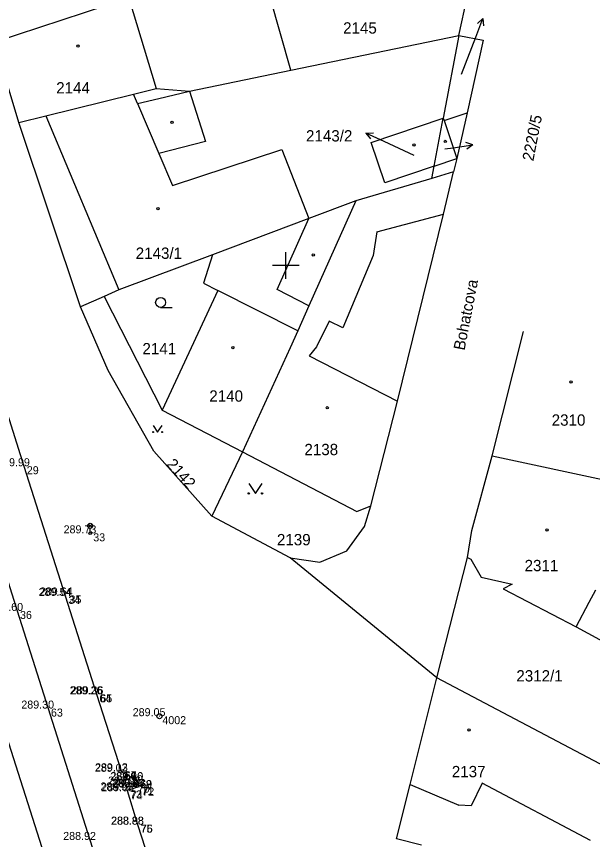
# Model space of a CAD drawing. Extents: x -599970 to -599524, y -1154772 to -1154457.
# Drawn here: x -599670.2 to -599627, y -1154593 to -1154531.3 of the extents above; entities that cross this region are included whole.
import ezdxf

# ---------------------------------------------------------------- set-up
doc = ezdxf.new("R2010")
doc.units = 0
for name, color, linetype in [('Z-ELEKTRICKE SKRINE LAMPY', 7, 'Continuous'), ('Z-KANALIZACNI SACHTY VPUSTI', 7, 'Continuous'), ('Z-KATASTRALNI MAPA', 7, 'Continuous'), ('Z-KRIZKY CTVERCOVE SITE', 7, 'Continuous'), ('Z-PEVNE BODY-CISLO', 7, 'Continuous'), ('Z-PEVNE BODY-VYSKA', 7, 'Continuous'), ('Z-PEVNE BODY-ZNACKA', 7, 'Continuous'), ('Z-PODROBNE BODY', 7, 'Continuous'), ('Z-PODROBNE BODY-CISLO', 7, 'Continuous'), ('Z-PODROBNE BODY-VYSKA', 7, 'Continuous'), ('Z-VODOROVNE ZNACENI', 7, 'Continuous'), ('Z-ZPEVNENE PLOCHY', 7, 'Continuous')]:
    doc.layers.add(name, color=color, linetype=linetype)

msp = doc.modelspace()

# ---------------------------------------------------------------- linework, layer by layer
at = {"layer": 'Z-ELEKTRICKE SKRINE LAMPY'}
for p, q in [((-599664.792, -1154569.659), (-599664.528, -1154569.395)), ((-599664.524, -1154569.658), (-599664.788, -1154569.393)), ((-599664.66, -1154569.99), (-599664.66, -1154569.715))]:
    msp.add_line(p, q, dxfattribs=at)
for centre, radius in [((-599664.66, -1154569.528), 0.188), ((-599664.66, -1154570.09), 0.1)]:
    msp.add_circle(centre, radius, dxfattribs=at)
at = {"layer": 'Z-KANALIZACNI SACHTY VPUSTI'}
msp.add_line((-599661.445, -1154588.93), (-599661.195, -1154588.93), dxfattribs=at)
msp.add_lwpolyline([(-599661.445, -1154589.055), (-599661.195, -1154589.055), (-599661.195, -1154588.805), (-599661.445, -1154588.805)], close=True, dxfattribs=at)
at = {"layer": 'Z-KATASTRALNI MAPA'}
for p, q in [((-599637.02, -1154532.76), (-599635.64, -1154526.2)), ((-599649.63, -1154535.37), (-599652, -1154526.95)), ((-599661.78, -1154529.94), (-599659.73, -1154536.73)), ((-599635.77, -1154532.89), (-599635.233, -1154531.489)), ((-599635.233, -1154531.489), (-599635.645, -1154531.867)), ((-599635.233, -1154531.489), (-599635.178, -1154532.046)), ((-599649.63, -1154535.37), (-599637.02, -1154532.76)), ((-599637.02, -1154532.76), (-599638.2, -1154538.95)), ((-599670.01, -1154539.29), (-599671.83, -1154533.26)), ((-599636.84, -1154535.67), (-599635.77, -1154532.89)), ((-599661.11, -1154537.86), (-599661.41, -1154537.15)), ((-599659.51, -1154537.48), (-599657.22, -1154536.94)), ((-599657.22, -1154536.94), (-599656.03, -1154540.71)), ((-599661.11, -1154537.86), (-599659.51, -1154537.48)), ((-599661.11, -1154537.86), (-599659.52, -1154541.61)), ((-599670.01, -1154539.29), (-599668, -1154538.79)), ((-599668, -1154538.79), (-599662.53, -1154551.84)), ((-599638.88, -1154542.56), (-599638.2, -1154538.95)), ((-599665.38, -1154553.11), (-599670.01, -1154539.29)), ((-599638.14, -1154539.14), (-599637.17, -1154541.98)), ((-599644, -1154540.076), (-599643.441, -1154540.061)), ((-599642.64, -1154540.71), (-599644, -1154540.076)), ((-599644, -1154540.076), (-599643.652, -1154540.515)), ((-599656.03, -1154540.71), (-599659.52, -1154541.61)), ((-599640.38, -1154541.75), (-599642.64, -1154540.71)), ((-599635.974, -1154540.971), (-599636.505, -1154540.793)), ((-599658.5, -1154544), (-599650.3, -1154541.32)), ((-599650.3, -1154541.32), (-599648.27, -1154546.48)), ((-599638.07, -1154541.26), (-599637.46, -1154541.18)), ((-599637.46, -1154541.18), (-599635.974, -1154540.971)), ((-599635.974, -1154540.971), (-599636.435, -1154541.289)), ((-599659.52, -1154541.61), (-599658.5, -1154544)), ((-599638.88, -1154542.56), (-599637.17, -1154541.98)), ((-599639.06, -1154543.48), (-599638.88, -1154542.56)), ((-599637.42, -1154542.99), (-599639.06, -1154543.48)), ((-599639.06, -1154543.48), (-599644.75, -1154545.16)), ((-599643.17, -1154547.49), (-599638.19, -1154546.17)), ((-599650.65, -1154551.8), (-599648.27, -1154546.48)), ((-599643.17, -1154547.49), (-599643.45, -1154549.26)), ((-599643.45, -1154549.26), (-599645.72, -1154554.68)), ((-599655.11, -1154551.87), (-599659.26, -1154560.85)), ((-599649.11, -1154554.9), (-599655.11, -1154551.87)), ((-599648.28, -1154553.04), (-599650.65, -1154551.8)), ((-599663.61, -1154552.33), (-599665.38, -1154553.11)), ((-599663.61, -1154552.33), (-599659.26, -1154560.85)), ((-599659.387, -1154553.15), (-599658.512, -1154553.15)), ((-599646.74, -1154554.18), (-599647.7, -1154556.11)), ((-599645.72, -1154554.68), (-599646.74, -1154554.18)), ((-599634.54, -1154564.27), (-599632.19, -1154554.95)), ((-599647.7, -1154556.11), (-599648.26, -1154556.79)), ((-599648.26, -1154556.79), (-599641.64, -1154560.17)), ((-599659.26, -1154560.85), (-599653.25, -1154563.98)), ((-599653.25, -1154563.98), (-599655.55, -1154568.8)), ((-599653.25, -1154563.98), (-599644.67, -1154568.46)), ((-599636.06, -1154569.88), (-599634.54, -1154564.27)), ((-599634.54, -1154564.27), (-599625.4, -1154566.23)), ((-599644.67, -1154568.46), (-599643.64, -1154568.04)), ((-599649.67, -1154571.93), (-599655.55, -1154568.8)), ((-599636.38, -1154571.9), (-599636.06, -1154569.88)), ((-599638.67, -1154580.93), (-599649.67, -1154571.93)), ((-599638.67, -1154580.93), (-599636.38, -1154571.9)), ((-599627.26, -1154575.25), (-599626.77, -1154574.32)), ((-599628.23, -1154577.1), (-599627.26, -1154575.25)), ((-599619.28, -1154591.18), (-599638.67, -1154580.93)), ((-599640.68, -1154588.93), (-599637.03, -1154590.47)), ((-599635.28, -1154588.82), (-599636.11, -1154590.53)), ((-599627.16, -1154593.12), (-599635.28, -1154588.82)), ((-599636.11, -1154590.53), (-599637.03, -1154590.47)), ((-599639.83, -1154593.48), (-599641.71, -1154593))]:
    msp.add_line(p, q, dxfattribs=at)
for points in [[(-599652, -1154526.95), (-599652.86, -1154526.99), (-599661.78, -1154529.94), (-599671.83, -1154533.26)], [(-599637.02, -1154532.76), (-599635.2, -1154533.11), (-599636.41, -1154538.55)], [(-599668, -1154538.79), (-599661.41, -1154537.15), (-599659.73, -1154536.73), (-599657.22, -1154536.94), (-599649.63, -1154535.37)], [(-599638.88, -1154542.56), (-599642.57, -1154543.81), (-599643.6, -1154540.79), (-599638.2, -1154538.95)], [(-599638.2, -1154538.95), (-599638.14, -1154539.14), (-599636.41, -1154538.55)], [(-599636.41, -1154538.55), (-599637.17, -1154541.98), (-599637.42, -1154542.99)], [(-599643.64, -1154568.04), (-599641.64, -1154560.17), (-599638.19, -1154546.17), (-599637.42, -1154542.99)], [(-599644.75, -1154545.16), (-599648.27, -1154546.48), (-599655.51, -1154549.21)], [(-599644.75, -1154545.16), (-599648.28, -1154553.04), (-599649.11, -1154554.9), (-599649.68, -1154556.18), (-599653.25, -1154563.98)], [(-599655.51, -1154549.21), (-599662.53, -1154551.84), (-599663.61, -1154552.33)], [(-599655.51, -1154549.21), (-599656.17, -1154551.33), (-599655.11, -1154551.87)], [(-599655.55, -1154568.8), (-599659.9, -1154563.93), (-599663.33, -1154557.88), (-599665.38, -1154553.11)], [(-599659.945, -1154561.997), (-599659.61, -1154562.5), (-599659.275, -1154561.997)], [(-599652.78, -1154566.35), (-599652.28, -1154567.1), (-599651.78, -1154566.35)], [(-599649.67, -1154571.93), (-599647.46, -1154572.26), (-599645.42, -1154571.39), (-599644.11, -1154569.57), (-599643.64, -1154568.04)], [(-599636.38, -1154571.9), (-599636.13, -1154572.03), (-599635.35, -1154573.38), (-599633.04, -1154573.91), (-599633.71, -1154574.25), (-599628.23, -1154577.1), (-599626.49, -1154578.05), (-599622.22, -1154580.39)], [(-599641.71, -1154593), (-599640.68, -1154588.93), (-599638.67, -1154580.93)]]:
    msp.add_lwpolyline(points, dxfattribs=at)
for centre, radius in [((-599665.583, -1154533.55), 0.0875), ((-599658.533, -1154539.27), 0.0875), ((-599638.053, -1154540.71), 0.0875), ((-599640.403, -1154540.97), 0.0875), ((-599659.593, -1154545.74), 0.0875), ((-599647.943, -1154549.21), 0.0875), ((-599659.386, -1154552.775), 0.375), ((-599653.973, -1154556.18), 0.0875), ((-599628.613, -1154558.74), 0.0875), ((-599646.893, -1154560.68), 0.0875), ((-599659.945, -1154562.5), 0.0335), ((-599659.275, -1154562.5), 0.0335), ((-599652.78, -1154567.1), 0.05), ((-599651.78, -1154567.1), 0.05), ((-599630.413, -1154569.84), 0.0875), ((-599636.263, -1154584.83), 0.0875)]:
    msp.add_circle(centre, radius, dxfattribs=at)
at = {"layer": 'Z-KRIZKY CTVERCOVE SITE'}
for p, q in [((-599650, -1154551), (-599650, -1154549)), ((-599649, -1154550), (-599651, -1154550))]:
    msp.add_line(p, q, dxfattribs=at)
at = {"layer": 'Z-PEVNE BODY-ZNACKA'}
for radius in [0.188, 0.188, 0.00896, 0.00896]:
    msp.add_circle((-599659.48, -1154583.8), radius, dxfattribs=at)
at = {"layer": 'Z-PODROBNE BODY'}
for p, q in [((-599669.64, -1154565.06), (-599669.64, -1154565.06)), ((-599664.66, -1154570.09), (-599664.66, -1154570.09)), ((-599666.53, -1154574.78), (-599666.53, -1154574.78)), ((-599666.44, -1154574.75), (-599666.44, -1154574.75)), ((-599670.15, -1154575.91), (-599670.15, -1154575.91)), ((-599664.2, -1154582.16), (-599664.2, -1154582.16)), ((-599664.13, -1154582.16), (-599664.13, -1154582.16)), ((-599667.83, -1154583.23), (-599667.83, -1154583.23)), ((-599662.32, -1154587.97), (-599662.32, -1154587.97)), ((-599662.3, -1154587.93), (-599662.3, -1154587.93)), ((-599661.32, -1154588.93), (-599661.32, -1154588.93)), ((-599661.17, -1154588.61), (-599661.17, -1154588.61)), ((-599661.14, -1154588.59), (-599661.14, -1154588.59)), ((-599661.9, -1154589.37), (-599661.9, -1154589.37)), ((-599661.84, -1154589.43), (-599661.84, -1154589.43)), ((-599661.03, -1154589.1), (-599661.03, -1154589.1)), ((-599660.98, -1154589.15), (-599660.98, -1154589.15)), ((-599661.11, -1154591.93), (-599661.11, -1154591.93)), ((-599661.09, -1154591.94), (-599661.09, -1154591.94))]:
    msp.add_line(p, q, dxfattribs=at)
at = {"layer": 'Z-VODOROVNE ZNACENI'}
for points in [[(-599694.02, -1154499.99), (-599689.54, -1154514.32), (-599685.46, -1154527.42), (-599683.24, -1154534.53), (-599677.91, -1154551.43), (-599673.26, -1154566.04), (-599670.15, -1154575.91), (-599664.69, -1154593.08), (-599661.63, -1154602.65), (-599657.71, -1154615.01), (-599654.33, -1154625.58), (-599650.3, -1154638.13), (-599646.03, -1154651.51), (-599641.58, -1154665.41), (-599629.85, -1154702.06), (-599625.38, -1154716.06)], [(-599697.63, -1154501.15), (-599693.46, -1154514.34), (-599689.12, -1154528.02), (-599685.9, -1154538.22), (-599681.17, -1154553.13), (-599676.65, -1154567.39), (-599673.59, -1154577), (-599671.31, -1154584.14), (-599668.11, -1154594.2), (-599666.34, -1154599.75), (-599661.15, -1154616.02), (-599657.79, -1154626.57), (-599653.82, -1154639.02), (-599649.52, -1154652.61), (-599645.03, -1154666.6), (-599639.28, -1154684.62), (-599637.35, -1154690.63), (-599633.4, -1154703.39)]]:
    msp.add_lwpolyline(points, dxfattribs=at)
at = {"layer": 'Z-ZPEVNENE PLOCHY'}
msp.add_lwpolyline([(-599687.9, -1154498.79), (-599683.81, -1154511.87), (-599681.17, -1154520.27), (-599680.7, -1154530), (-599680.59, -1154530.5), (-599678.7, -1154536.46), (-599674.09, -1154550.98), (-599669.64, -1154565.06), (-599666.53, -1154574.78), (-599664.2, -1154582.16), (-599662.32, -1154587.97), (-599661.17, -1154588.61), (-599661.03, -1154589.1), (-599661.9, -1154589.37), (-599661.11, -1154591.93), (-599657.79, -1154602.2), (-599654.15, -1154613.66), (-599652.29, -1154619.52), (-599651.12, -1154620.18), (-599650.97, -1154620.63), (-599651.85, -1154620.91), (-599651.44, -1154622.26)], dxfattribs=at)

# ---------------------------------------------------------------- texts
at = {"layer": 'Z-KATASTRALNI MAPA'}
for s, p in [('2145', (-599645.708, -1154532.62)), ('2144', (-599667.215, -1154537.11)), ('2143/2', (-599648.489, -1154540.71)), ('2143/1', (-599661.254, -1154549.51)), ('2141', (-599660.751, -1154556.67)), ('2140', (-599655.738, -1154560.22)), ('2310', (-599630.071, -1154562.02)), ('2138', (-599648.608, -1154564.23)), ('2139', (-599650.668, -1154570.99)), ('2311', (-599632.104, -1154572.93)), ('2312/1', (-599632.72, -1154581.2)), ('2137', (-599637.558, -1154588.38))]:
    msp.add_text(s, height=0.85, dxfattribs=at).set_placement(p)
for s, rotation, p in [('2220/5', 79, (-599631.45, -1154542.22)), ('Bohatcova', 79, (-599636.607, -1154556.414)), ('2142', 312, (-599659.007, -1154564.952))]:
    msp.add_text(s, height=0.85, rotation=rotation, dxfattribs=at).set_placement(p)
at = {"layer": 'Z-PEVNE BODY-CISLO'}
msp.add_text(' 4002', height=0.6, dxfattribs=at).set_placement((-599659.48, -1154584.4))
at = {"layer": 'Z-PEVNE BODY-VYSKA'}
msp.add_text('289.05 ', height=0.6, dxfattribs=at).set_placement((-599661.48, -1154583.8))
at = {"layer": 'Z-PODROBNE BODY-CISLO'}
for s, p in [(' 29', (-599669.64, -1154565.66)), (' 33', (-599664.66, -1154570.69)), (' 34', (-599666.53, -1154575.38)), (' 35', (-599666.44, -1154575.35)), (' 36', (-599670.15, -1154576.51)), (' 64', (-599664.2, -1154582.76)), (' 65', (-599664.13, -1154582.76)), (' 63', (-599667.83, -1154583.83)), (' 66', (-599662.32, -1154588.57)), (' 67', (-599662.3, -1154588.53)), (' 70', (-599661.32, -1154589.53)), (' 68', (-599661.17, -1154589.21)), (' 69', (-599661.14, -1154589.19)), (' 73', (-599661.9, -1154589.97)), (' 74', (-599661.84, -1154590.03)), (' 71', (-599661.03, -1154589.7)), (' 72', (-599660.98, -1154589.75)), (' 75', (-599661.11, -1154592.53)), (' 76', (-599661.09, -1154592.54))]:
    msp.add_text(s, height=0.6, dxfattribs=at).set_placement(p)
at = {"layer": 'Z-PODROBNE BODY-VYSKA'}
for s, p in [('289.99 ', (-599671.64, -1154565.06)), ('289.73 ', (-599666.66, -1154570.09)), ('289.54 ', (-599668.53, -1154574.78)), ('289.64 ', (-599668.44, -1154574.75)), ('289.60 ', (-599672.15, -1154575.91)), ('289.26 ', (-599666.2, -1154582.16)), ('289.36 ', (-599666.13, -1154582.16)), ('289.30 ', (-599669.83, -1154583.23)), ('289.02 ', (-599664.32, -1154587.97)), ('289.13 ', (-599664.3, -1154587.93)), ('288.96 ', (-599663.32, -1154588.93)), ('288.96 ', (-599663.17, -1154588.61)), ('289.10 ', (-599663.14, -1154588.59)), ('288.97 ', (-599663.9, -1154589.37)), ('289.08 ', (-599663.84, -1154589.43)), ('288.95 ', (-599663.03, -1154589.1)), ('289.07 ', (-599662.98, -1154589.15)), ('288.88 ', (-599663.11, -1154591.93)), ('288.98 ', (-599663.09, -1154591.94)), ('288.92 ', (-599666.69, -1154593.08))]:
    msp.add_text(s, height=0.6, dxfattribs=at).set_placement(p)

doc.saveas('drawing.dxf')
